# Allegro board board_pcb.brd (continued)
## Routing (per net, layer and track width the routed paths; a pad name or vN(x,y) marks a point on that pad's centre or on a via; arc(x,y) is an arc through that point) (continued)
N30264: length 3
  TOP w0.152: U37.1 73.94,17 73.79,17.15 73.79,17.78 74.27,18.26 R1373.1 R406.2
N30402: length 1.3
  TOP w0.254: 77.09,17.02 76.57,16.5 U37.9
N30450: length 1.9
  TOP w0.254: C1485.2 77.79,16 U37.8
N34682: length 4.2
  TOP w0.249: 32.85,41.57 33.15,41.27 U4.3
  TOP w0.305: 32.85,41.57 32,42.42 32,42.8 31.85,42.95 R1739.1 R14.2
N51448: length 8.1
  TOP w0.152: U135.24 82.16,87.64 82.68,87.12 R1747.1
N51452: length 1.4
  TOP w0.152: D113.2 81.35,80.24 R1747.2
N56281: length 2.1
  TOP w0.305: R1749.1 83.82,51.56
N56705: length 1
  TOP w0.305: R86.2 R1615.1
N56737: length 2.1
  TOP w0.305: U26.7 78.66,53.4 R176.1
N56741: length 2
  TOP w0.305: R176.2 78.11,55.73 R1748.1 78.08,56.72 R1615.2
N57183: length 1.8
  TOP w0.305: U26.8 80.48,52.75 80.87,52.35 R1749.2
N60036: length 1.7
  TOP w0.152: R1751.1 D117.1
N60157: length 1.7
  TOP w0.152: R1752.1 D118.1
N61083: length 1.6
  TOP w0.152: R1755.1 29.44,39.24 D121.1
N61087: length 1.4
  TOP w0.152: D122.1 30.07,43.43 R1756.1
N8840853: length 3.5
  TOP w0.152: U133.21 58.95,20.57 58.04,19.66 58.04,19.46 R1733.1
N8856572: length 2.5
  TOP w0.152: R32.1 C356.2 48.23,49.5 X3.3
N8887240: length 6.9
  TOP w0.152: U1.C12 v2(46.87,66.05) ; R281.2 v2(42.04,67.94)
  BOTTOM w0.152: v2(42.04,67.94) 42.55,67.44 44.32,67.44 45.71,66.05 v2(46.87,66.05)
N8887299: length 5.3
  TOP w0.152: R1224.2 43.41,66.62 44.55,66.62 44.73,66.45 U1.A13
N8887317: length 6
  TOP w0.152: R1225.2 41.81,65.66 43.18,67.03 44.78,67.03 44.97,66.85 46.07,66.85 U1.B13
N8887321: length 9
  TOP w0.152: R1223.2 v2(42.04,70.23) ; U1.E14 v2(48.47,67.65)
  BOTTOM w0.152: v2(48.47,67.65) 48.07,68.05 45.9,68.05 45.67,68.27 45.67,68.68 45.51,68.85 44.79,68.85 43.41,70.23 v2(42.04,70.23)
N8887325: length 8.7
  TOP w0.152: U1.E13 v2(48.47,66.85) ; R1222.2 v2(42.04,69.09)
  BOTTOM w0.152: v2(42.04,69.09) 43.69,69.09 45.53,67.25 48.07,67.25 v2(48.47,66.85)
N8887398: length 7.7
  TOP w0.152: v2(42.04,66.93) 41.91,66.8 R1221.2 ; U1.D12 v2(47.67,66.05)
  BOTTOM w0.152: v2(42.04,66.93) 42.55,66.42 44.7,66.42 45.51,65.61 47.24,65.61 v2(47.67,66.05)
N8915420: length 1.4
  TOP w0.305: U1.U11 v2(58.87,65.25)
  BOTTOM w0.305: v2(58.87,65.25) 59.23,65.61 C1945.2
N8916004: length 1.6
  TOP w0.305: U1.A7 44.88,61.65 v2(44.83,61.59)
  BOTTOM w0.305: C1947.2 45.21,61.21 v2(44.83,61.59)
N8924132: length 3.7
  TOP w0.152: U3.48 22.07,79.84 22.23,79.99 R1766.1
N8924451: length 5.6
  TOP w0.152: U3.38 22.32,74.84 22.61,74.55 22.61,72.16 R1767.1
N8924569: length 2.4
  TOP w0.152: R1768.1 20.02,70.55 U3.36
N16774766: length 3.8
  TOP w0.152: U3.32 18.02,71.54 R1769.1 R946.1
N16774923: length 3.5
  TOP w0.152: R1774.1 R1770.2 16.89,71.37 16.52,71.74 U3.29
N16774927: length 2.9
  TOP w0.152: U3.28 16.02,71.67 R1775.1
N16775135: length 3.7
  TOP w0.152: R1776.1 R1773.1 13.84,70.99 14.52,71.67 U3.25
N16776183: length 4.5
  TOP w0.152: U3.37 22.05,74.34 22.23,74.17 22.23,71.53 R1777.1
N16776304: length 5.4
  TOP w0.152: U3.42 22.73,76.84 24.26,75.31 24.26,74.14 R1783.1
N16776308: length 5
  TOP w0.152: R1778.1 24.87,75.34 22.86,77.34 U3.43
N16776812: length 1.9
  TOP w0.305: X5.1 30.15,75.08 R1781.1
N16777866: length 2.8
  TOP w0.254: R1786.1 13.82,82.55 14.73,82.55 15.02,82.26 U3.11
N16777871: length 5.4
  TOP w0.254: U3.12 14.52,81.79 14.27,82.04 13.31,82.04 R1784.1 11.79,82.91 11.18,82.3 Q18.2
N16777887: length 2.8
  TOP w0.254: U3.14 10.78,79.34 R1855.2
N16778460: length 2.8
  TOP w0.152: R1787.2 10.83,76.34 U3.20
N16778536: length 3.7
  TOP w0.152: R1848.2 R1788.2 10.56,76.84 U3.19
N16779520: length 4.2
  TOP w0.305: R1855.1 8.53,78.99 8,79.53 8,80.26 Q18.1
N16781751: length 33.5
  TOP w0.305: J3.9 22.73,102.37 16.26,102.37 15.49,101.6 9.78,101.6 7.24,99.06 7.24,90.17 10.54,86.87 R1790.2
N16781754: length 22.3
  TOP w0.305: R1791.2 5.71,89.31 5.71,100.08 9.56,103.92 J3.12
N16783015: length 6
  TOP w0.305: v1(19.79,86.74) 19.79,86.03 20.09,85.72 C1961.2 20.89,86.3 21.34,86.74 v1(22.38,86.74)
  BOTTOM w0.305: R1794.1 v1(19.79,86.74) ; R1793.1 v1(22.38,86.74)
N16783029: length 5.4
  TOP w0.305: v1(13.06,86.74) 13.94,85.85 C1962.2 15.3,86.4 v1(15.65,86.74)
  BOTTOM w0.305: R1796.1 v1(13.06,86.74) ; R1795.1 v1(15.65,86.74)
N16791902: length 11.5
  TOP w0.152: U1.E7 v2(48.47,62.05) ; R1797.2 R1798.2 41.76,59.94 v2(42.29,59.41)
  BOTTOM w0.152: v2(42.29,59.41) 42.32,59.44 45.34,59.44 45.53,59.25 47.87,59.25 48.07,59.45 48.07,61.41 48.47,61.81 v2(48.47,62.05)
N16792692: length 3.1
  TOP w0.152: R1854.2 48.69,85.85 S10.1
N16792994: length 2.7
  TOP w0.152: S7.1 85.98,87.78 R1856.2
N16847649: length 2.3
  TOP w0.249: 32.42,37.75 32.65,37.98 U4.5
  TOP w0.305: 32.42,37.75 31.75,37.08 R20.2
N16850956: length 1.4
  TOP w0.381: R1806.2 76.07,9.65 76.2,9.78 D133.2
N16850985: length 1.4
  TOP w0.381: R1807.2 69.09,50.93 69.34,51.18 D132.2
N16872883: length 4.6
  TOP w0.152: U1.N4 v2(55.67,58.85)
  BOTTOM w0.152: v2(55.67,58.85) 55.04,58.85 54.48,58.29 54.48,57.8 54.33,57.65 52.72,57.65 R1782.1
N16886716: length 1.4
  TOP w0.305: U1.D17 v2(47.67,70.05)
  BOTTOM w0.305: C1946.2 47.62,70.09 v2(47.67,70.05)
N16890832: length 5.2
  TOP w0.203: 56.27,21.2 56.89,21.2 56.95,21.26 U133.16
  TOP w0.305: 56.27,21.2 56.15,21.32 55.42,21.32 54.74,20.63 54.74,20.29 R1853.1
N16908117: length 6.5
  TOP w0.152: U2.H3 72.48,63.23 73.91,63.23 74.04,63.09 74.54,63.09 R1851.2
N16908318: length 5.7
  TOP w0.152: U2.J2 73.29,64.03 73.93,64.03 74.17,64.26 74.55,64.26 R1849.2
N16914135: length 1.7
  TOP w0.152: R1626.1 30.53,7.39 D74.1
N16971823:
  vias: v1(104.65,5.71) v1(104.65,4.45) v1(104.65,3.17) v1(105.92,5.71) v1(105.92,4.45) v1(105.92,3.17) v1(107.19,5.71) v1(107.19,4.45) v1(107.19,3.17) v1(108.46,5.71) v1(108.46,4.45) v1(108.46,3.17) v1(109.73,5.71) v1(109.73,4.45) v1(109.73,3.17)
N17017170: length 2.7
  TOP w0.152: U140.4 41.83,42.72 R50.1 R1673.1
N17038390: length 2.5
  TOP w0.305: D134.2 67.46,28.97 R1868.2 68.43,29.59 R1867.1
N17051637: length 2.7
  TOP w0.152: U141.3 v1(55.38,41.43)
  BOTTOM w0.305: R1863.2 55.4,43.26 R1864.1 55.4,41.45 v1(55.38,41.43)
N17051655: length 1.8
  TOP w0.254: U141.5 v1(54.88,37.47)
  BOTTOM w0.305: R1862.2 v1(54.88,37.47)
N17071435: length 1
  TOP w0.305: R1868.1 66.67,29.57 R1869.1
N19175875: length 1.5
  TOP w0.254: C1791.2 89.89,40.25 U8.7
N19175881: length 2.6
  TOP w0.254: U8.8 88.12,41.64 88.39,41.91 89.64,41.91 R1608.2
N19175893: length 3.9
  TOP w0.254: v2(86.6,40.01) v2(86.6,40.44) 86.62,40.46 U8.11 86.62,42.61 v1(86.61,42.62) ; v2(86.6,39.57) 86.62,39.55 U8.2
  TOP w0.305: v2(86.6,39.57) v2(86.6,40.01)
  vias: v1(85.85,42.62)
N19175909: length 1.6
  TOP w0.254: R1605.1 89.63,39.76 U8.6
N19176042: length 3.7
  TOP w0.254: U8.5 88.12,38.37 88.39,38.1 88.77,38.1 89.05,38.38 R1602.1 R1604.1
N19176179: length 2.6
  TOP w0.254: R1599.1 87.12,42.19 U8.10
N19176181: length 3.8
  TOP w0.254: R1599.2 C1779.2 88.84,46.16 89.15,46.48 89.15,46.86 89.63,47.34 D112.1
N19179790: length 1
  TOP w0.254: R1608.1 R1609.1
N19180483: length 3.1
  TOP w0.254: C1789.1 R1606.1 R1607.1 91.72,39.37 R1605.2
N19180998: length 1
  TOP w0.254: C1789.2 93.75,40.39 R1603.2
N19211433: length 4.3
  TOP w0.254: U8.4 87.62,37.98 89.05,36.55 R142.1 89.05,35.1 R85.2
N19540928: length 1
  TOP w0.254: R1607.2 91.82,41.25 R1610.1
N19572988: length 1.8
  TOP w0.305: U132.8 60.16,33.95 60.55,33.55 R1611.2
N19573046: length 2.1
  TOP w0.305: U132.7 58.87,34.6 58.32,35.15 R1477.1
N19573048: length 2
  TOP w0.305: R1613.1 57.76,37.92 R1475.1 57.78,36.93 R1477.2
N19576360: length 1
  TOP w0.305: R1613.2 R1612.2
N88478500: length 2.8
  TOP w0.152: R1742.1 17.17,63.6 S5.1
N88479500: length 2.8
  TOP w0.152: R267.1 8.74,64.82 8.3,64.39 S3.1
N88497910: length 2.8
  TOP w0.152: S6.1 58.6,84.76 R1745.1
N167922400: length 2.7
  TOP w0.152: R1802.1 53.01,84.76 S11.1

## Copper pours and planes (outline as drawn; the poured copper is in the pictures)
1V2 on TOP (solid shape): 69.6,73.76 79.76,73.76 83.67,69.85 83.67,65.35 86.49,62.53 86.49,60.45 88.77,58.17 88.77,56.64 88.71,56.58 84.39,56.58 84.33,56.64 84.33,57.4 83.95,57.78 82.42,57.78 82.3,57.91 82.3,61.98 83.06,61.98 83.06,62.36 82.55,62.36 82.55,61.98 82.3,61.98 82.31,62.02 82.32,62.07 82.32,62.1 82.32,62.61 82.32,62.64 82.31,62.7 82.3,62.73 82.3,62.99 82.17,63.12 81.03,63.12 80.77,63.37 80.77,68.55 77.95,71.37 68.71,71.37 64.52,75.56 63.77,75.56 63.75,75.57 59.47,75.57 59.18,75.85 59.18,77.22 59.56,77.6 65.76,77.6
1V2 on BOTTOM (solid shape): 84.14,64.07 84.14,57.98 83.95,57.78 82.42,57.78 82.3,57.91 82.3,63.12 82.17,63.25 80.9,63.25 80.77,63.37 80.77,63.88 81.03,64.14 84.07,64.14
1V2 on BOTTOM (solid shape): 61.21,75.82 61.21,75.72 59.79,74.3 57.99,74.3 57.78,74.35 57.58,74.3 56.91,74.3 56.71,74.35 56.5,74.3 56.26,74.3 56.19,74.32 56.13,74.32 55.63,74.32 55.56,74.31 55.5,74.3 55.37,74.42 55.37,75.18 55.75,75.56 58.55,75.56 58.56,75.56 58.8,75.56 59.23,76 61.04,76
2V5 on TOP (solid shape): 57.78,45.59 57.78,42.19 57.02,41.43 57.02,40.51 56.85,40.34 55.88,40.34 55.79,40.42 55.79,41.06 55.88,41.15 55.88,44.7 55.8,44.78 55.8,44.96 56.39,44.96 56.39,45.34 56.01,45.34 56.01,44.96 55.8,44.96 55.8,45.64 55.88,45.72 57.66,45.72
2V5 on TOP (solid shape): 55.12,55.88 55.12,54.01 55.09,54 54.92,53.88 54.82,53.69 54.82,53.68 53.85,52.7 53.59,52.7 53.47,52.83 53.47,53.85 54.48,54.86 54.48,55.3 54.48,55.34 54.48,55.75 54.36,55.88 54.36,56.26 54.43,56.34 54.54,56.34 54.61,56.36 54.63,56.36
2V5 on ART03 (solid shape): 54.37,54.21 54.37,52.32 54.4,52.19 54.48,52.07 56.39,50.16 56.42,50.13 58.04,48.51 58.04,44.07 57.78,43.81 55.5,43.81 55.24,44.07 55.24,48.72 53.34,50.62 53.34,54.1 53.47,54.23 54.36,54.23
3V3 on TOP (solid shape): 9.6,69.65 9.6,68.83 9.65,68.78 9.65,67.94 9.53,67.82 7.49,67.82 7.37,67.94 7.37,68.96 9.4,68.96 9.4,69.34 9.02,69.34 9.02,68.96 7.37,68.96 7.37,69.6 7.49,69.72 9.53,69.72
3V3 on TOP (solid shape): 41.27,43.31 41.27,40.77 41.15,40.64 40.13,40.64 39.88,40.89 39.88,42.67 40.89,42.67 40.89,43.18 40.51,43.18 40.51,42.67 39.88,42.67 39.88,43.31 40.01,43.43 41.15,43.43
3V3 on TOP (solid shape): 51.94,105.66 51.94,103.89 50.29,102.23 50.27,102.24 50.23,102.25 50.19,102.26 50.16,102.26 49.66,102.26 49.63,102.26 49.57,102.25 49.53,102.23 48.64,102.23 48.51,102.36 48.51,102.49 49.91,102.49 49.91,103 49.53,103 49.53,102.49 48.51,102.49 48.51,103.63 50.67,105.79 51.82,105.79
3V3 on TOP (solid shape): 65.38,87.37 65.4,87.35 65.45,87.32 65.5,87.29 65.56,87.27 65.62,87.26 65.77,87.26 66.29,86.74 68.45,86.74 68.61,86.59 68.61,85.7 68.45,85.55 63.25,85.55 63.12,85.67 63.12,85.72 65.66,85.72 65.66,86.23 65.28,86.23 65.28,85.72 63.12,85.72 63.12,87.38 63.25,87.5 65.25,87.5
3V3 on TOP (solid shape): 37.29,9.7 37.29,4.78 36.58,4.06 35.31,4.06 35.18,4.19 35.18,6.35 35.56,6.73 35.56,7.11 37.08,7.11 37.08,7.49 36.7,7.49 36.7,7.11 35.56,7.11 35.56,8.13 37.08,8.13 37.08,8.51 36.7,8.51 36.7,8.13 35.56,8.13 35.56,9.91 35.69,10.03 36.96,10.03
3V3 on TOP (solid shape): 77.34,7.7 80.44,7.7 80.64,7.49 80.64,6.48 80.26,6.1 79.5,6.1 79.38,5.97 79.38,5.84 79.36,5.8 79.35,5.74 79.35,5.71 79.35,5.21 79.35,5.18 79.25,5.08 76.83,5.08 76.71,5.21 76.71,5.46 79.12,5.46 79.12,5.84 78.74,5.84 78.74,5.46 76.71,5.46 76.71,7.11 78.99,7.11 78.99,7.49 78.61,7.49 78.61,7.11 77.98,7.11 77.98,7.49 77.6,7.49 77.6,7.11 76.71,7.11 77.32,7.72
3V3 on TOP (solid shape): 44.45,91.06 44.45,89.79 44.32,89.66 44.3,89.67 44.26,89.68 44.22,89.69 44.2,89.69 43.69,89.69 43.66,89.69 43.6,89.68 43.56,89.66 43.3,89.66 43.27,89.68 43.21,89.69 43.18,89.69 42.67,89.69 42.64,89.69 42.59,89.68 42.55,89.66 41.27,89.66 41.02,89.92 44.32,89.92 44.32,90.42 43.94,90.42 43.94,89.92 43.31,89.92 43.31,90.42 42.93,90.42 42.93,89.92 41.02,89.92 40.89,90.04 40.89,91.06 41.02,91.19 44.32,91.19
3V3 on TOP (solid shape): 60.33,36.96 60.33,35.99 60.27,35.94 60.27,35.76 60.25,35.74 59.06,35.74 59.03,35.73 58.89,35.69 58.79,35.58 58.77,35.56 58.53,35.56 58.45,35.59 58.39,35.61 58.37,35.61 58.34,35.64 58.34,36.25 58.5,36.4 58.83,36.4 59.04,36.49 59.13,36.7 59.13,37.03 59.18,37.08 60.2,37.08
3V3 on TOP (solid shape): 5.23,62.09 5.27,62.08 5.31,62.08 5.33,62.08 5.84,62.08 5.87,62.08 5.93,62.09 5.97,62.1 6.23,62.1 6.26,62.09 6.32,62.08 6.35,62.08 6.86,62.08 6.89,62.08 6.94,62.09 6.98,62.1 7.75,62.1 7.87,61.98 7.87,59.05 7.37,58.55 5.46,58.55 5.08,58.93 5.08,61.34 6.99,61.34 6.99,61.85 6.6,61.85 6.6,61.34 5.97,61.34 5.97,61.85 5.59,61.85 5.59,61.34 5.08,61.34 5.08,61.98 5.21,62.1
3V3 on TOP (solid shape): 57.12,38.3 57.12,34.82 57.4,34.54 58.04,34.54 58.17,34.42 58.17,33.66 56.77,32.26 56.52,32.26 56.34,32.44 56.34,34.47 56.06,34.75 56.06,35.18 56.64,35.18 56.64,35.56 56.26,35.56 56.26,35.18 56.06,35.18 56.06,35.94 56.64,35.94 56.64,36.32 56.26,36.32 56.26,35.94 56.06,35.94 56.06,37.52 55.8,37.78 55.8,38.11 55.81,38.2 55.81,38.62 55.88,38.69 56.43,38.69 56.49,38.7 56.73,38.7
3V3 on TOP (solid shape): 66.17,48.77 66.17,45.47 66.42,45.21 68.45,45.21 68.83,45.59 68.83,48.01 69.09,48.26 72.9,48.26 73.03,48.13 73.03,44.32 72.64,43.94 70.48,43.94 70.1,43.56 67.44,43.56 67.18,43.31 67.18,40.39 68.45,39.12 68.45,37.85 68.39,37.79 63.96,37.79 63.96,37.72 63.88,37.72 63.5,37.34 63.5,36.83 63.37,36.7 62.87,36.7 62.74,36.83 62.74,38.1 61.98,38.86 61.98,44.58 62.74,44.58 62.74,44.96 62.23,44.96 62.23,44.58 61.98,44.58 61.99,44.62 62,44.67 62,44.7 62,45.21 62,45.24 61.99,45.3 61.98,45.34 61.98,45.59 61.85,45.72 60.58,45.72 60.45,45.85 60.45,46.48 60.58,46.61 62.74,46.61 62.99,46.86 62.99,47.5 63.01,47.54 63.02,47.6 63.02,47.62 63.02,47.88 63.75,47.88 63.75,48.26 63.25,48.26 63.25,47.88 63.02,47.88 63.02,48.13 63.02,48.16 63.01,48.22 62.99,48.26 62.99,48.51 63.07,48.59 63.53,48.59 63.55,48.59 63.61,48.6 63.66,48.62 63.7,48.64 63.75,48.64 64.01,48.9 66.04,48.9
3V3 on BOTTOM (solid shape): 64.9,87.25 64.9,85.72 64.77,85.6 63.37,85.6 63.12,85.85 63.12,87.09 63.4,87.37 64.77,87.37
3V3 on BOTTOM (solid shape): 73.03,47.24 73.03,44.45 72.9,44.32 71.37,44.32 71.25,44.45 71.25,47.24 71.5,47.5 72.77,47.5
3V3 on BOTTOM (solid shape): 52.17,103.05 53.57,103.05 53.85,102.77 53.85,100.79 53.64,100.58 53.01,100.58 52.83,100.76 52.83,101.93 52.58,102.18 48.97,102.18 48.77,102.39 48.77,103.68 48.95,103.86 51.36,103.86
3V3 on BOTTOM (solid shape): 66.17,47.62 66.17,43.81 65.79,43.43 62.36,43.43 61.72,44.07 61.72,45.72 61.59,45.85 60.58,45.85 60.45,45.97 60.45,46.86 60.64,47.05 62.29,47.05 63.12,47.88 65.91,47.88
3V3 on BOTTOM (solid shape): outline of 321 points within 56.26,32.26 64.14,39.24
3V3 on ART06 (solid shape): outline of 16589 points within 4.06,4.57 97.16,104.27
3V9 on TOP (solid shape): 28.17,46.91 29.06,46.91 29.24,46.74 33.05,46.74 33.32,46.46 33.32,45.54 33.66,45.21 33.66,42.8 34.42,42.04 34.42,40.51 34.29,40.39 33.66,40.39 33.53,40.51 33.53,41.53 32.51,42.55 32.51,44.32 32.26,44.58 30.48,44.58 30.35,44.7 31.37,44.7 31.37,45.09 30.99,45.09 30.99,44.7 30.35,44.7 30.23,44.83 28.57,44.83 27.69,45.72 33.02,45.72 33.02,46.1 32.64,46.1 32.64,45.72 27.69,45.72 27.56,45.85 24,45.85 23.88,45.97 23.88,46.35 28.96,46.35 28.96,46.74 28.57,46.74 28.57,46.35 23.88,46.35 23.88,47.12 24.13,47.37 27.71,47.37
5V0 on TOP (solid shape): 73.91,38.1 73.91,34.29 73.79,34.16 71.12,34.16 70.99,34.29 70.99,37.97 71.25,38.23 73.79,38.23
5V0 on TOP (solid shape): 94.23,56.9 94.23,53.09 94.11,52.96 91.44,52.96 91.31,53.09 91.31,56.77 91.57,57.02 94.11,57.02
5V0 on TOP (solid shape): 121.41,104.65 121.41,103.12 121.36,103.07 119.04,103.07 119.04,104.31 119.51,104.78 121.28,104.78
5V0 on TOP (solid shape): 135.25,103.12 135.25,93.98 135,93.73 133.73,93.73 133.35,94.11 133.35,98.17 132.46,99.06 132.46,99.82 132.97,99.82 132.97,100.2 132.59,100.2 132.59,99.82 132.46,99.82 132.46,103.25 132.59,103.38 135,103.38
5V0 on TOP (solid shape): 83.82,47.62 83.82,42.42 83.19,41.78 83.19,39.24 82.93,38.99 75.31,38.99 74.93,39.37 74.93,45.09 75.82,45.09 75.82,45.47 75.44,45.47 75.44,45.09 74.93,45.09 74.93,45.47 75.18,45.72 75.44,45.72 75.48,45.71 75.54,45.69 75.56,45.69 76.07,45.69 76.1,45.69 76.58,45.21 80.39,45.21 80.64,45.47 80.64,47.37 81.15,47.88 83.57,47.88
5V0 on TOP (solid shape): 34.39,38.76 34.39,37.39 34.11,37.11 34.11,35.2 33.71,34.8 33.71,33.27 33.58,33.15 30.86,33.15 30.73,33.27 30.73,34.8 31.01,35.08 32.18,35.08 32.33,35.23 32.33,35.31 33.91,35.31 33.91,35.69 33.53,35.69 33.53,35.31 32.33,35.31 32.33,36.32 33.91,36.32 33.91,36.7 33.53,36.7 33.53,36.32 32.33,36.32 32.33,36.93 33.5,38.1 33.5,38.73 33.63,38.86 34.29,38.86
5V0 on BOTTOM (solid shape): 75.48,45.71 75.54,45.69 75.56,45.69 76.07,45.69 76.1,45.69 76.58,45.21 80.52,45.21 80.64,45.09 80.64,42.29 80.39,42.04 75.18,42.04 74.93,42.29 74.93,45.09 75.82,45.09 75.82,45.47 75.44,45.47 75.44,45.09 74.93,45.09 74.93,45.47 75.18,45.72 75.44,45.72
5V0 on BOTTOM (solid shape): 122.05,106.17 122.05,103.12 121.54,102.62 119.63,102.62 119.38,102.87 119.38,103.12 119.89,103.12 119.89,103.5 119.51,103.5 119.51,103.12 119.38,103.12 119.38,103.76 119.89,103.76 119.89,104.14 119.51,104.14 119.51,103.76 119.38,103.76 119.38,104.52 119.63,104.78 120.4,104.78 120.78,105.16 120.78,106.3 120.9,106.43 121.79,106.43
5V0 on POWER05 (solid shape): outline of 14480 points within 23.24,29.59 135.51,105.54
AGND on TOP (solid shape): 12.57,24.13 12.57,20.7 12.45,20.57 10.29,20.57 10.16,20.7 10.16,24.26 10.29,24.38 12.32,24.38
AGND on TOP (solid shape): 29.34,31.75 29.34,29.08 29.21,28.96 28.07,28.96 27.94,29.08 27.94,31.75 28.07,31.88 29.21,31.88
AGND on TOP (solid shape): 35.56,45.72 35.56,39.52 35.18,39.14 32.59,39.14 30.96,40.77 30.96,41.4 31.11,41.55 32.23,41.55 32.77,41.02 32.77,40.26 32.92,40.11 34.85,40.11 35.08,40.34 35.08,41.88 34.04,42.93 34.04,45.31 33.76,45.59 34.42,45.59 34.42,46.1 33.91,46.1 33.91,45.59 33.76,45.59 33.71,45.64 33.71,46.56 33.12,47.14 32.36,47.14 32.13,47.37 29.59,47.37 29.51,47.29 28.4,47.29 28.32,47.37 28.32,47.5 28.96,47.5 28.96,47.88 28.57,47.88 28.57,47.5 28.32,47.5 28.32,48.01 28.83,48.51 32.77,48.51
AGND on TOP (solid shape): outline of 445 points within 0.51,0.51 25.91,57.53
AGND on BOTTOM (solid shape): outline of 1654 points within 0.51,0.51 35.56,57.53
AGND on GND02 (solid shape): outline of 1717 points within 0.51,0.51 35.56,57.53
AGND on ART03 (solid shape): outline of 1750 points within 0.51,0.51 35.56,64.64
AGND on GND04 (solid shape): outline of 1717 points within 0.51,0.51 35.56,57.53
AGND on POWER05 (solid shape): outline of 1717 points within 0.51,0.51 35.56,57.53
AGND on ART06 (solid shape): outline of 1707 points within 0.51,0.51 35.56,57.53
AGND on GND07 (solid shape): outline of 1717 points within 0.51,0.51 35.56,57.53
AGND on ART08 (solid shape): outline of 1717 points within 0.51,0.51 35.56,57.53
AGND on GND09 (solid shape): outline of 1717 points within 0.51,0.51 35.56,57.53
AVDD1V8 on TOP (solid shape): 32.89,87.63 32.89,83.82 32.77,83.69 24.89,83.69 24.64,83.95 24.64,88.52 24.89,88.77 31.75,88.77
AVDD1V8 on POWER05 (solid shape): outline of 1568 points within 12.32,76.96 35.31,93.98
GND on TOP (solid shape): 9.91,44.7 9.91,43.43 9.78,43.31 5.97,43.31 5.84,43.43 5.84,44.7 5.97,44.83 9.78,44.83
GND on TOP (solid shape): 27.81,49.78 27.81,48.77 27.43,48.39 24,48.39 23.88,48.51 23.88,49.78 24,49.91 27.69,49.91
GND on TOP (solid shape): 32.38,31.62 32.38,29.08 32.26,28.96 30.48,28.96 30.35,29.08 30.35,31.75 30.48,31.88 32.13,31.88
GND on TOP (solid shape): 34.16,94.11 34.16,92.08 33.91,91.82 32.26,91.82 32.13,91.95 32.13,94.11 32.26,94.23 34.04,94.23
GND on TOP (solid shape): 37.97,80.01 37.97,77.47 37.85,77.34 36.45,77.34 36.32,77.47 36.32,80.01 36.45,80.14 37.85,80.14
GND on TOP (solid shape): 41.02,94.74 41.02,91.82 40.89,91.69 40.39,91.69 40.26,91.82 40.26,94.74 40.39,94.87 40.89,94.87
GND on TOP (solid shape): 42.04,33.15 42.04,30.48 41.91,30.35 35.43,30.35 35.18,30.61 35.18,31.97 36.48,33.27 41.91,33.27
GND on TOP (solid shape): 53.98,30.61 53.98,25.65 53.85,25.53 52.2,25.53 52.07,25.65 52.07,30.61 52.32,30.86 53.72,30.86
GND on TOP (solid shape): 84.71,25.27 84.71,21.08 84.45,20.83 81.53,20.83 81.41,20.95 81.41,25.27 81.66,25.53 84.45,25.53
GND on TOP (solid shape): 73.35,13.77 73.35,12.65 73.28,12.57 72.9,12.57 72.77,12.7 71.88,12.7 71.75,12.83 71.75,13.54 71.93,13.72 72.77,13.72 72.9,13.84 73.28,13.84
GND on TOP (solid shape): 50.29,101.85 50.29,100.33 50.16,100.2 48.64,100.2 48.51,100.33 48.51,101.22 49.91,101.22 49.91,101.73 49.53,101.73 49.53,101.22 48.51,101.22 48.51,101.85 48.59,101.93 50.22,101.93
GND on TOP (solid shape): 87.76,15.37 87.76,12.19 87.38,11.81 85.22,11.81 85.09,11.94 85.09,13.84 87.63,13.84 87.63,14.22 87.25,14.22 87.25,13.84 85.09,13.84 85.09,15.37 85.22,15.49 87.63,15.49
GND on TOP (solid shape): 46.23,20.19 46.23,16.89 46.1,16.76 42.42,16.76 42.29,16.89 42.29,18.54 42.16,18.67 42.16,19.94 42.42,20.19 44.45,20.19 44.7,20.45 45.97,20.45
GND on TOP (solid shape): 80.26,48.26 80.26,45.72 80.14,45.59 76.83,45.59 76.33,46.1 75.56,46.1 75.44,46.23 76.2,46.23 76.2,46.61 75.82,46.61 75.82,46.23 75.44,46.23 75.44,48.13 75.69,48.39 80.14,48.39
GND on TOP (solid shape): 41.27,44.96 41.27,43.81 41.21,43.75 40.32,43.75 40.13,43.94 40.89,43.94 40.89,44.45 40.51,44.45 40.51,43.94 40.13,43.94 39.5,44.58 39.5,44.96 39.62,45.09 41.15,45.09
GND on TOP (solid shape): 68.55,85.09 68.55,84.12 68.48,84.05 66.9,84.05 66.17,83.31 63.25,83.31 63.12,83.44 63.12,84.45 65.66,84.45 65.66,84.96 65.28,84.96 65.28,84.45 63.12,84.45 63.12,85.09 63.2,85.17 68.48,85.17
GND on TOP (solid shape): 68.45,54.36 68.45,45.85 68.2,45.59 66.8,45.59 66.55,45.85 66.55,48.45 66.55,48.46 66.55,48.87 66.55,48.88 66.55,49.35 66.6,49.4 66.6,53.47 67.31,53.47 67.31,53.85 66.8,53.85 66.8,53.47 66.6,53.47 66.6,54.41 66.67,54.48 68.33,54.48
GND on TOP (solid shape): 23.88,75.15 23.88,74.14 23.88,74.13 23.88,73.41 24.77,72.52 25.3,72.52 25.3,72.24 25.33,72.09 25.41,71.97 26.29,71.09 26.29,70.74 26.16,70.74 25.27,71.63 24.77,71.63 23.37,73.02 23.37,75.18 23.5,75.31 23.72,75.31
GND on TOP (solid shape): 41.91,57.4 41.91,56.39 41.78,56.26 40.64,56.26 40.39,56.01 38.61,56.01 38.35,55.75 37.72,55.75 37.47,56.01 35.69,56.01 35.56,56.13 35.56,56.52 41.4,56.52 41.4,56.9 41.02,56.9 41.02,56.52 35.56,56.52 35.56,57.4 35.71,57.56 41.76,57.56
GND on TOP (solid shape): 57.09,31.43 57.09,30.67 57.28,30.48 57.28,27.3 57.15,27.18 56.9,27.18 56.39,26.67 54.48,26.67 54.36,26.8 54.36,30.73 56.9,30.73 56.9,31.11 56.52,31.11 56.52,30.73 54.36,30.73 54.36,31.37 54.61,31.62 56.9,31.62
GND on TOP (solid shape): 69.22,9.53 69.22,8 70.1,7.11 72.77,7.11 73.15,6.73 73.15,4.19 73.41,3.94 78.36,3.94 78.74,3.56 78.74,2.16 79.63,1.27 79.63,0.64 79.5,0.51 67.39,0.51 67.31,0.59 67.31,8.13 67.06,8.38 67.06,9.53 67.18,9.65 69.09,9.65
GND on TOP (solid shape): 39.75,48.39 40.89,48.39 41.02,48.26 41.02,47.37 40.77,47.12 38.86,47.12 38.79,47.19 38.79,47.5 39.37,47.5 39.37,47.88 38.99,47.88 38.99,47.5 38.79,47.5 38.79,48.13 39.37,48.13 39.37,48.51 38.99,48.51 38.99,48.13 38.79,48.13 38.79,48.69 38.86,48.77 39.37,48.77
GND on TOP (solid shape): 42.8,40.26 42.8,38.1 42.34,37.64 42.34,37.21 42.27,37.13 41.58,37.13 41.5,37.21 41.5,37.47 42.16,37.47 42.16,37.85 41.78,37.85 41.78,37.47 41.5,37.47 41.5,37.92 41.66,38.07 41.66,40.26 41.78,40.39 42.67,40.39
GND on TOP (solid shape): 36.2,37.72 36.2,34.67 35.18,33.66 34.59,33.66 34.42,33.83 34.42,35.26 34.47,35.31 35.05,35.31 35.05,35.69 34.67,35.69 34.67,35.31 34.47,35.31 34.47,36.32 35.05,36.32 35.05,36.7 34.67,36.7 34.67,36.32 34.47,36.32 34.47,37.01 34.73,37.27 34.73,37.66 34.92,37.85 36.07,37.85
GND on TOP (solid shape): 39.88,8.89 39.88,5.46 39.75,5.33 37.97,5.33 37.62,5.69 37.62,6.73 38.23,6.73 38.23,7.11 37.85,7.11 37.85,6.73 37.62,6.73 37.62,7.75 38.23,7.75 38.23,8.13 37.85,8.13 37.85,7.75 37.62,7.75 37.62,9.04 37.72,9.14 39.62,9.14
GND on TOP (solid shape): 55.75,9.78 55.75,0.59 55.67,0.51 27.01,0.51 26.92,0.59 26.92,3.43 27.18,3.68 39.24,3.68 40.26,4.7 40.26,8.13 41.27,9.14 43.43,9.14 43.56,9.02 43.56,8.51 43.31,8.26 43.31,1.52 43.56,1.27 50.67,1.27 51.08,1.68 51.08,8.1 50.16,9.02 50.16,10.16 50.55,10.54 54.99,10.54
GND on TOP (solid shape): 91.06,59.94 91.06,56.95 91.01,56.9 91.01,52.96 91.06,52.91 91.06,52.07 90.93,51.94 86.03,51.94 85.9,52.07 85.72,52.07 85.68,52.08 85.63,52.1 85.6,52.1 85.19,52.1 85.09,52.2 85.09,52.32 85.72,52.32 85.72,52.83 85.34,52.83 85.34,52.32 85.09,52.32 85.09,53.47 85.22,53.59 89.03,53.59 89.15,53.72 89.15,58.29 88.01,59.44 88.01,59.82 88.27,60.07 90.93,60.07
GND on TOP (solid shape): 37.29,91.11 37.29,88.21 37.21,88.14 35.05,88.14 34.92,88.27 34.92,88.39 37.08,88.39 37.08,88.77 36.58,88.77 36.58,88.39 34.92,88.39 34.92,89.41 37.08,89.41 37.08,89.79 36.58,89.79 36.58,89.41 34.92,89.41 34.92,89.79 35.18,90.04 35.69,90.04 35.81,90.17 35.81,90.42 37.08,90.42 37.08,90.81 36.58,90.81 36.58,90.42 35.81,90.42 35.81,90.9 36.1,91.19 37.21,91.19
GND on TOP (solid shape): 45.34,15.62 45.34,13.87 44.83,13.36 41,13.36 40.89,13.46 40.89,13.59 44.7,13.59 44.7,13.97 44.32,13.97 44.32,13.59 43.69,13.59 43.69,13.97 43.31,13.97 43.31,13.59 42.67,13.59 42.67,13.97 42.29,13.97 42.29,13.59 41.66,13.59 41.66,13.97 41.27,13.97 41.27,13.59 40.89,13.59 40.89,15.62 41.02,15.75 45.21,15.75
GND on TOP (solid shape): 73.53,43.05 73.53,39.24 73.03,38.73 70.99,38.73 70.74,38.48 70.74,38.15 70.69,38.1 70.69,34.16 70.74,34.11 70.74,33.27 70.61,33.15 65.71,33.15 65.58,33.27 65.4,33.27 65.36,33.29 65.31,33.3 65.28,33.3 64.87,33.3 64.77,33.4 64.77,33.53 65.41,33.53 65.41,34.04 65.02,34.04 65.02,33.53 64.77,33.53 64.77,34.67 64.9,34.8 68.71,34.8 68.83,34.92 68.83,38.84 70.85,40.86 70.85,41.03 70.87,41.05 70.87,43.18 70.99,43.31 73.28,43.31
GND on TOP (solid shape): 85.72,41.91 86.11,41.91 86.23,41.78 86.23,37.97 85.72,37.47 85.72,32.51 85.34,32.13 84.07,32.13 83.82,31.88 83.82,30.23 83.69,30.1 80.9,30.1 80.26,30.73 73.91,30.73 73.41,30.23 73.41,27.18 73.28,27.05 69.98,27.05 69.72,27.3 69.72,30.35 69.91,30.54 72.96,30.54 75.31,32.89 75.31,34.67 75.56,34.92 83.06,34.92 83.19,35.05 83.19,37.59 83.69,38.1 83.69,41.53 84.33,42.16 85.47,42.16
GND on TOP (solid shape): 59,19.68 59,13.92 59.08,13.84 59.08,13.41 59,13.34 57.91,13.34 57.78,13.46 57.78,15.68 57.8,15.7 57.82,15.74 57.83,15.78 57.84,15.83 57.84,15.85 57.84,17.17 57.84,17.2 57.83,17.25 57.81,17.3 57.78,17.34 57.78,17.46 57.81,17.49 57.83,17.55 57.84,17.6 57.84,17.63 57.84,18.54 58.8,18.54 58.8,18.92 58.42,18.92 58.42,18.54 57.84,18.54 57.84,18.71 58.31,19.19 58.33,19.21 58.36,19.26 58.39,19.31 58.41,19.37 58.42,19.43 58.42,19.5 58.78,19.86 58.83,19.86
GND on TOP (solid shape): 75.56,54.61 75.56,49.66 75.18,49.27 75.11,49.22 74.61,48.71 74.55,48.64 74.42,48.51 74.42,43.56 74.3,43.43 73.77,43.43 73.75,43.45 73.71,43.49 73.67,43.51 73.62,43.53 73.57,43.55 73.55,43.55 73.53,43.56 73.53,48.9 73.41,49.02 73.41,52.45 73.42,52.49 73.43,52.55 73.43,52.58 73.43,52.83 74.17,52.83 74.17,53.21 73.66,53.21 73.66,52.83 73.43,52.83 73.43,53.09 73.43,53.12 73.42,53.17 73.41,53.21 73.41,54.61 73.53,54.74 75.44,54.74
GND on TOP (solid shape): 80.77,5.59 80.77,5.21 81.03,4.95 81.16,4.95 81.19,4.94 81.25,4.93 81.28,4.93 81.79,4.93 81.82,4.93 81.87,4.94 81.91,4.95 82.17,4.95 82.21,4.94 82.27,4.93 82.3,4.93 82.8,4.93 82.83,4.93 82.87,4.93 82.91,4.94 82.93,4.95 83.06,4.83 83.06,3.05 82.8,2.79 79.88,2.79 79.63,3.05 79.63,4.19 82.55,4.19 82.55,4.7 82.17,4.7 82.17,4.19 81.92,4.19 81.92,4.7 81.53,4.7 81.53,4.19 79.63,4.19 79.63,5.03 79.68,5.08 79.68,5.64 79.76,5.71 80.64,5.71
GND on TOP (solid shape): 60.45,45.41 61.58,45.41 61.66,45.34 61.66,44.34 61.52,44.2 61.52,38.73 62.36,37.9 62.36,36.58 62.87,36.07 62.87,35.84 62.76,35.74 61.52,35.74 61.5,35.72 61.49,35.71 61.34,35.71 61.21,35.59 61.21,34.67 61.09,34.54 60.71,34.54 60.63,34.62 60.62,34.8 60.62,34.85 60.6,34.89 60.58,34.94 60.55,34.98 60.52,35.01 60.48,35.04 60.44,35.06 60.39,35.08 60.34,35.08 60.32,35.08 59.15,35.08 59.05,35.18 59.05,35.31 59.17,35.42 60.32,35.42 60.34,35.42 60.39,35.42 60.45,35.43 60.48,35.47 60.5,35.48 60.54,35.51 60.56,35.54 60.6,35.6 60.62,35.64 60.62,35.7 60.63,35.86 60.71,35.94 60.71,37.08 60.33,37.47 59.46,37.47 59.31,37.62 59.31,44.58 61.47,44.58 61.47,44.96 60.96,44.96 60.96,44.58 59.31,44.58 59.31,45 59.75,45.43 60.43,45.43
GND on TOP (solid shape): 75.12,17.77 75.21,17.72 75.31,17.7 75.82,17.7 75.93,17.72 76.02,17.78 76.2,17.78 76.33,17.65 76.33,17.02 76.24,16.93 75.75,16.93 75.45,16.81 75.32,16.5 75.34,16.37 75.4,16.25 75.34,16.13 75.32,16 75.45,15.7 75.75,15.57 76.63,15.57 76.71,15.49 76.71,13.08 76.58,12.95 75.44,12.95 75.18,13.21 75.18,13.97 74.85,14.3 74.85,15.11 74.8,15.16 74.8,15.32 74.98,15.49 74.8,15.67 74.8,17.53 75.06,17.78 75.11,17.78
GND on TOP (solid shape): 81.75,62.7 81.95,62.7 81.99,62.66 81.99,61.87 81.84,61.72 81.84,57.53 82.22,57.15 83.19,57.15 83.39,56.95 83.39,54.61 83.31,54.53 81.84,54.53 81.82,54.51 81.81,54.51 81.66,54.51 81.53,54.38 81.53,53.47 81.41,53.34 81.03,53.34 80.95,53.42 80.94,53.6 80.94,53.65 80.92,53.69 80.9,53.73 80.87,53.77 80.84,53.81 80.8,53.83 80.76,53.86 80.71,53.87 80.66,53.88 80.64,53.88 79.47,53.88 79.38,53.98 79.38,54.1 79.49,54.21 80.64,54.21 80.66,54.21 80.71,54.22 80.77,54.23 80.83,54.28 80.88,54.32 80.92,54.39 80.94,54.44 80.94,54.49 80.95,54.52 80.95,54.87 80.94,54.9 80.94,54.95 80.92,55 80.9,55.04 80.9,55.14 79.63,56.41 79.63,61.98 81.79,61.98 81.79,62.36 81.28,62.36 81.28,61.98 79.63,61.98 80.39,62.74 81.71,62.74
GND on TOP (solid shape): 65.91,30.73 65.91,26.29 65.79,26.16 64.24,26.16 63.22,25.15 63.22,22.12 64.01,21.34 66.8,21.34 67.06,21.08 67.06,14.1 66.93,13.97 64.64,13.97 64.52,14.1 64.52,20.57 64.17,20.92 63.84,20.92 62.48,22.28 61.85,22.28 61.65,22.48 62.48,22.48 62.48,22.86 62.1,22.86 62.1,22.48 61.65,22.48 61.21,22.91 61.21,23.09 61.04,23.27 58.42,23.27 58.15,23 57.34,23 57.23,23.11 57.23,24.21 57.38,24.36 58.09,24.36 58.24,24.21 58.24,23.55 58.32,23.47 61.06,23.47 61.25,23.66 61.25,23.88 62.48,23.88 62.48,24.26 62.1,24.26 62.1,23.88 61.25,23.88 61.25,23.89 61.82,24.46 62.64,24.46 62.79,24.61 62.79,25.65 63.12,25.98 63.12,30.73 63.25,30.86 65.79,30.86
GND on TOP (solid shape): 43.43,54.1 43.43,53.98 43.33,53.87 42.21,53.87 42.07,53.84 41.95,53.76 41.19,53.01 40.92,53.01 40.84,53 40.77,52.97 40.69,53 40.61,53.01 40.11,53.01 39.92,52.94 39.81,52.77 39.81,52.76 39.75,52.7 39.75,52.07 39.62,51.94 39.62,49.53 39.75,49.4 43.69,49.4 43.81,49.53 43.81,49.65 43.82,49.72 43.82,51.5 43.81,51.56 43.81,51.94 43.69,52.07 43.69,52.45 43.81,52.58 44.07,52.58 44.21,52.72 44.27,52.75 44.31,52.79 45.75,54.23 45.94,54.23 45.97,54.15 45.97,53.72 44.22,51.97 44.14,51.85 44.11,51.7 44.11,49.48 43.4,48.77 39.88,48.77 39.16,49.48 39.17,49.53 39.17,50.8 39.15,50.89 39.12,50.97 39.12,52.83 39.43,53.14 40.07,53.14 40.12,53.15 40.18,53.16 41.02,53.16 42.16,54.3 43.23,54.3
GND on TOP (solid shape): 25.4,76.07 32.89,76.07 33.02,75.95 33.02,70.99 32.77,70.74 31.95,70.74 31.94,70.74 31.63,70.74 31.62,70.74 30.73,70.74 30.72,70.74 30.41,70.74 30.4,70.74 29.51,70.74 29.5,70.74 29.19,70.74 29.18,70.74 28.29,70.74 28.28,70.74 27.21,70.74 27.05,70.9 27.05,71.25 27.05,71.31 27.03,71.37 27.05,71.46 27.13,71.5 30.83,71.5 30.84,71.47 30.95,71.34 31.11,71.3 31.62,71.3 31.81,71.36 31.92,71.53 31.92,71.55 32.13,71.75 32.13,72.8 32.19,72.92 32.21,73.05 32.21,73.89 32.19,74.02 32.13,74.14 32.13,75.44 32,75.56 31.83,75.56 31.73,75.62 31.62,75.64 31.11,75.64 31.01,75.62 30.91,75.56 28.32,75.56 28.19,75.44 28.19,75.26 28.17,75.26 28.17,74.28 27.94,74.04 26.67,74.04 26.42,74.3 26.42,74.93 26.04,75.31 25.25,75.31 25.25,75.36 25.21,75.49 25.14,75.61 23.13,77.61 23.01,77.69 22.86,77.72 22.74,77.72 22.61,77.85 22.61,78.11 22.73,78.23 23.24,78.23
GND on TOP (solid shape): outline of 124 points within 53.47,32.13 56.39,45.75
GND on TOP (solid shape): outline of 99 points within 45.21,46.61 52.7,56.01
GND on TOP (solid shape): outline of 548 points within 0.51,58.55 67.44,109.49
GND on TOP (solid shape): outline of 765 points within 66.67,0.51 139.49,109.49
GND on BOTTOM (solid shape): 57.28,39.62 57.28,38.61 57.02,38.35 54.86,38.35 54.74,38.48 54.74,39.75 54.86,39.88 57.02,39.88
GND on BOTTOM (solid shape): 64.9,84.96 64.9,83.57 64.77,83.44 63.25,83.44 63.12,83.57 63.12,84.96 63.25,85.09 64.77,85.09
GND on BOTTOM (solid shape): 89.79,9.65 89.79,6.86 89.41,6.48 87,6.48 86.61,6.86 86.61,9.6 86.92,9.91 89.53,9.91
GND on BOTTOM (solid shape): 67.06,21.21 67.06,15.75 66.93,15.62 64.39,15.62 64.26,15.75 64.26,21.08 64.52,21.34 66.93,21.34
GND on BOTTOM (solid shape): 68.45,54.36 68.45,45.85 68.2,45.59 66.8,45.59 66.55,45.85 66.55,50.37 66.6,50.42 66.6,54.41 66.67,54.48 68.33,54.48
GND on BOTTOM (solid shape): 50.93,34.54 50.93,32.64 50.74,32.45 50.36,32.45 50.29,32.38 46.99,32.38 46.86,32.51 46.86,34.92 47.12,35.18 50.29,35.18
GND on BOTTOM (solid shape): 75.56,54.61 75.56,49.66 74.42,48.51 74.42,43.56 74.3,43.43 73.66,43.43 73.53,43.56 73.53,48.9 73.41,49.02 73.41,54.61 73.53,54.74 75.44,54.74
GND on BOTTOM (solid shape): 25.4,52.07 27.69,52.07 28.22,51.54 28.22,49.25 27.35,48.39 11.09,48.39 10.29,47.58 10.29,35.9 10.08,35.69 4.78,35.69 3.94,36.53 3.94,52.83 4.57,53.47 24,53.47
GND on BOTTOM (solid shape): 57.28,31.37 57.28,28.19 57.15,28.07 56.26,28.07 56.01,27.81 56.01,26.8 55.75,26.54 54.61,26.54 54.36,26.8 54.36,29.46 55.37,30.48 55.37,31.5 55.5,31.62 57.02,31.62
GND on BOTTOM (solid shape): 85.5,42.06 85.5,37.06 85.72,36.83 85.72,31.62 85.47,31.37 75.9,31.37 75.59,31.67 75.59,39.8 76.17,40.39 82.22,40.39 83.19,41.35 83.19,42.16 83.31,42.29 85.27,42.29
GND on BOTTOM (solid shape): 80.26,48.26 80.26,45.72 80.14,45.59 76.83,45.59 76.33,46.1 75.56,46.1 75.44,46.23 76.2,46.23 76.2,46.61 75.82,46.61 75.82,46.23 75.44,46.23 75.44,48.13 75.69,48.39 80.14,48.39
GND on BOTTOM (solid shape): 59.05,18.29 59.05,13.46 58.93,13.34 57.78,13.34 57.66,13.46 57.66,15.16 57.71,15.37 57.66,15.57 57.66,18.29 57.78,18.41 58.93,18.41
GND on BOTTOM (solid shape): 120.02,106.3 120.02,105.16 119.94,105.08 119.51,105.08 119.46,105.03 119.38,105.03 118.87,104.52 118.87,102.74 118.75,102.62 117.98,102.62 117.6,103 117.6,103.12 118.75,103.12 118.75,103.5 118.36,103.5 118.36,103.12 117.6,103.12 117.6,103.76 118.75,103.76 118.75,104.14 118.36,104.14 118.36,103.76 117.6,103.76 117.6,106.17 117.86,106.43 119.89,106.43
GND on BOTTOM (solid shape): 61.34,45.28 61.34,43.81 62.23,42.93 70.48,42.93 70.87,43.31 73.28,43.31 73.53,43.05 73.53,39.24 73.03,38.73 70.99,38.73 70.74,38.48 70.74,33.27 70.61,33.15 62.1,33.15 60.58,34.67 60.58,34.92 60.83,35.18 63.63,35.18 64.64,36.2 64.64,39.37 64.26,39.75 61.72,39.75 61.34,39.37 61.34,39.12 60.96,38.73 59.56,38.73 59.31,38.99 59.31,45.34 59.4,45.43 61.18,45.43
GND on BOTTOM (solid shape): 53.59,64.64 53.59,61.85 53.47,61.72 50.67,61.72 50.55,61.85 50.55,62.14 50.56,62.16 50.58,62.21 50.61,62.25 50.62,62.3 50.63,62.36 50.64,62.41 50.64,62.56 50.63,62.61 50.62,62.66 50.6,62.72 50.58,62.77 50.55,62.83 50.55,63.16 50.56,63.18 50.58,63.22 50.61,63.27 50.62,63.32 50.63,63.37 50.64,63.43 50.64,63.57 50.63,63.63 50.62,63.68 50.6,63.73 50.58,63.78 50.55,63.84 50.55,64.18 50.56,64.19 50.58,64.24 50.61,64.29 50.62,64.34 50.63,64.39 50.64,64.44 50.64,64.59 50.63,64.64 50.62,64.71 50.67,64.77 53.47,64.77
GND on BOTTOM (solid shape): 81.53,62.74 81.53,57.78 81.92,57.4 82.8,57.4 83.24,56.97 82.74,56.46 80.64,56.46 80.47,56.43 80.32,56.33 79.68,55.69 79.58,55.54 79.55,55.37 79.68,55.04 80,54.91 80.18,54.94 80.33,55.04 80.83,55.55 82.93,55.55 83.11,55.58 83.25,55.68 84.14,56.57 84.23,56.69 84.27,56.83 84.27,56.84 86.23,58.8 86.23,59.69 86.61,60.07 90.81,60.07 91.06,59.82 91.06,52.07 90.93,51.94 79.63,51.94 79.12,52.45 79.12,56.13 79.31,56.26 79.43,56.45 79.63,56.64 79.63,62.61 79.88,62.87 81.41,62.87
GND on BOTTOM (solid shape): outline of 169 points within 39.12,45.97 52.45,52.7
GND on BOTTOM (solid shape): outline of 1038 points within 26.92,0.51 55.75,41.15
GND on BOTTOM (solid shape): outline of 3405 points within 0.51,0.51 139.49,109.49
GND on GND02 (solid shape): outline of 35350 points within 0.51,0.51 139.49,109.49
GND on ART03 (solid shape): outline of 18571 points within 0.51,0.51 139.49,109.49
GND on GND04 (solid shape): outline of 35351 points within 0.51,0.51 139.49,109.49
GND on POWER05 (solid shape): outline of 15990 points within 0.51,0.51 139.49,109.49
GND on ART06 (solid shape): 49.54,22.97 49.53,22.86 49.53,16.13 49.53,16.1 49.54,16.03 49.56,15.97 49.58,15.9 49.62,15.85 49.66,15.79 49.68,15.77 55.75,9.7 55.75,0.59 55.67,0.51 27.01,0.51 26.92,0.59 26.92,4.83 28.07,5.97 31.52,5.97 31.55,5.95 31.61,5.93 31.68,5.91 31.74,5.9 31.81,5.89 31.88,5.9 31.95,5.91 32.01,5.93 32.07,5.95 32.1,5.97 37.08,5.97 37.72,6.6 37.72,10.03 36.07,11.68 36.07,13.33 41.99,13.33 41.99,10.29 43.38,8.89 43.38,6.6 44.07,5.92 50.29,5.92 50.72,6.35 50.72,12.95 50.04,13.64 42.29,13.64 41.99,13.33 36.07,13.33 36.07,24.26 36.45,24.64 47.88,24.64
GND on ART06 (solid shape): outline of 1052 points within 3.94,35.69 31.5,65.15
GND on ART06 (solid shape): outline of 10177 points within 0.51,0.51 139.49,109.49
GND on GND07 (solid shape): outline of 35351 points within 0.51,0.51 139.49,109.49
GND on ART08 (solid shape): outline of 1226 points within 58.8,30.99 77.47,53.59
GND on ART08 (solid shape): outline of 16619 points within 0.51,0.51 139.49,109.49
GND on GND09 (solid shape): outline of 35351 points within 0.51,0.51 139.49,109.49
GND_SIGNAL on TOP (solid shape): 35.31,80.01 35.31,77.34 35.18,77.22 25.02,77.22 23.62,78.61 22.73,78.61 22.61,78.74 22.61,79.76 22.94,80.09 35.23,80.09
GND_SIGNAL on TOP (solid shape): 24.13,88.27 24.13,84.2 23.37,83.44 22.67,83.44 22.64,83.46 22.59,83.48 22.53,83.49 22.5,83.49 22,83.49 21.84,83.64 21.84,83.69 22.73,83.69 22.73,84.33 22.23,84.33 22.23,83.69 21.84,83.69 21.84,84.33 21.97,84.45 21.97,86.11 22.86,86.11 23.11,86.36 23.11,87.12 22.86,87.38 18.29,87.38 17.14,86.23 17.14,85.6 17.02,85.47 16.38,85.47 16.26,85.6 16.26,87.12 17.59,88.46 23.94,88.46
GND_SIGNAL on BOTTOM (solid shape): outline of 515 points within 21.62,76.96 35.31,92.95
GND_SIGNAL on GND02 (solid shape): outline of 1481 points within 12.32,76.96 35.31,93.98
GND_SIGNAL on ART03 (solid shape): outline of 1481 points within 12.32,76.96 35.31,93.98
GND_SIGNAL on GND04 (solid shape): outline of 1481 points within 12.32,76.96 35.31,93.98
GND_SIGNAL on ART06 (solid shape): outline of 1480 points within 12.32,76.96 35.31,93.98
GND_SIGNAL on GND07 (solid shape): outline of 1481 points within 12.32,76.96 35.31,93.98
GND_SIGNAL on ART08 (solid shape): outline of 1481 points within 12.32,76.96 35.31,93.98
GND_SIGNAL on GND09 (solid shape): outline of 1481 points within 12.32,76.96 35.31,93.98
VBAT on TOP (solid shape): 43.81,55.75 43.81,55.12 43.31,54.61 42.04,54.61 40.89,53.47 38.1,53.47 37.85,53.21 37.85,51.94 37.72,51.82 36.07,51.82 35.94,51.94 35.94,53.21 35.69,53.47 35.69,54.86 35.81,54.99 40.13,54.99 40.26,55.12 41.78,55.12 41.78,55.5 41.4,55.5 41.4,55.12 40.26,55.12 40.89,55.75 41.91,55.75 42.04,55.88 43.69,55.88
VBAT on TOP (solid shape): 59.84,21.74 59.84,20.8 60.21,20.44 60.22,20.41 60.25,20.36 60.28,20.32 60.32,20.28 60.37,20.24 60.41,20.21 60.44,20.2 61.28,19.37 61.28,13.21 61.85,12.64 61.85,12.45 61.72,12.32 59.69,12.32 59.56,12.45 59.56,17.81 59.39,17.98 59.39,18.54 59.94,18.54 59.94,18.92 59.56,18.92 59.56,18.54 59.39,18.54 59.39,19.77 59.25,19.91 59.25,21.76 59.31,21.82 59.77,21.82
VBAT on TOP (solid shape): 93.98,17.4 93.98,11.94 93.73,11.68 88.9,11.68 88.39,12.19 88.39,13.46 88.27,13.59 88.27,13.84 88.77,13.84 88.77,14.22 88.39,14.22 88.39,13.84 88.27,13.84 88.27,15.62 88.01,15.88 85.09,15.88 84.71,15.49 84.71,13.21 84.58,13.08 84.56,13.09 84.52,13.1 84.48,13.11 84.45,13.11 83.95,13.11 83.93,13.11 83.88,13.1 83.84,13.09 83.82,13.08 83.74,13.16 83.74,13.34 84.58,13.34 84.58,13.84 84.2,13.84 84.2,13.34 83.74,13.34 83.74,13.61 83.74,13.64 83.74,13.68 83.72,13.72 83.71,13.76 83.69,13.78 83.69,16.64 84.71,17.65 93.73,17.65
VBAT on BOTTOM (solid shape): 46.35,55.12 45.34,54.1 43.49,54.1 43.48,54.15 43.34,54.42 43.05,54.53 42.95,54.52 42.86,54.49 42.85,54.48 42.67,54.48 42.04,55.12 42.04,55.75 42.29,56.01 43.43,56.01 43.69,55.75 43.69,55.12 43.74,55.06 43.86,54.95 44.01,54.91 44.77,54.91 44.88,54.93 44.97,54.99 45.21,54.99 45.47,55.24 45.47,56.03 45.65,56.19 45.73,56.42 45.73,56.46 46.35,56.46
VBAT on BOTTOM (solid shape): outline of 1139 points within 59.56,6.1 92.58,18.03
VBAT on ART08 (solid shape): outline of 3804 points within 39.69,10.54 71.75,56.13
VBUS on TOP (solid shape): outline of 130 points within 36.83,5.87 50.04,13.46
VBUS on ART06 (solid shape): outline of 360 points within 42.29,6.22 50.42,13.34
VBUS on ART08 (solid shape): outline of 360 points within 42.29,6.22 50.42,13.34
VBUS_OUT on TOP (solid shape): 45.09,33.53 45.09,33.15 43.43,31.5 43.43,29.08 42.16,27.81 42.16,26.29 41.78,25.91 35.31,25.91 35.18,26.04 35.18,29.72 35.31,29.84 42.04,29.84 42.35,30.16 42.35,32.19 43.81,33.66 44.96,33.66
VBUS_OUT on TOP (solid shape): 59.82,33.27 59.82,32.38 59.99,32.21 60.63,32.21 60.71,32.13 60.71,26.62 59.84,25.76 59.84,24.99 59.79,24.94 59.28,24.94 59.26,24.97 59.26,26.5 59.27,26.52 59.29,26.58 59.3,26.64 59.3,26.7 59.29,26.76 59.27,26.82 59.26,26.84 59.26,27.1 59.18,27.18 58.17,27.18 58.04,27.3 58.04,30.35 57.47,30.92 57.47,31.11 58.04,31.11 58.04,31.5 57.66,31.5 57.66,31.11 57.47,31.11 57.47,31.56 57.28,31.75 57.28,32.26 58.42,33.4 59.69,33.4
VBUS_OUT on BOTTOM (solid shape): 60.71,33.02 60.71,28.45 60.45,28.19 58.42,28.19 58.04,28.57 58.04,31.62 57.91,31.75 57.51,31.75 57.44,31.78 57.37,31.8 57.35,31.8 57.28,31.88 57.28,32.38 58.29,33.4 60.33,33.4
VBUS_OUT on ART06 (solid shape): outline of 2296 points within 35.24,25.15 60.83,35.43
VCC_COMB on TOP (solid shape): 39.24,45.72 39.24,45.14 39.19,45.08 39.19,44.45 39.24,44.4 39.24,43.56 39.12,43.43 38.23,43.43 38.1,43.56 38.1,45.21 38.86,45.21 38.86,45.59 38.35,45.59 38.35,45.21 38.1,45.21 38.1,45.85 38.2,45.95 38.61,45.95 38.64,45.95 38.69,45.96 38.73,45.97 38.99,45.97
VCC_COMB on TOP (solid shape): outline of 298 points within 59.74,10.16 73.66,25.91
VCC_COMB on BOTTOM (solid shape): 72.14,25.35 72.14,16.89 71.88,16.64 68.2,16.64 68.07,16.76 68.07,25.27 68.45,25.65 71.83,25.65
VCC_COMB on BOTTOM (solid shape): 63.88,20.7 63.88,15.88 63.63,15.62 61.85,15.62 61.59,15.88 61.59,20.83 61.72,20.95 63.63,20.95
VCC_COMB on ART03 (solid shape): outline of 2281 points within 38.1,21.97 71.63,47.82
VCC_SYS on TOP (solid shape): 80.58,29.4 83.76,29.4 84.2,28.96 84.28,28.96 84.28,28.76 88.69,28.76 88.71,28.77 88.77,28.7 88.77,26.16 88.65,26.04 81.15,26.04 80.77,25.65 80.77,20.5 80.72,20.45 80.72,19.76 80.64,19.68 79.25,19.68 78.87,20.07 80.52,20.07 80.52,20.45 80.01,20.45 80.01,20.07 78.87,20.07 78.23,20.7 76.83,20.7 76.71,20.83 76.71,26.92 77.22,27.43 77.22,29.72 77.47,29.97 80.01,29.97
VDD1V2 on BOTTOM (solid shape): 55.37,73.99 56.19,73.99 56.26,73.91 56.26,73.03 56.05,72.82 55.99,72.84 55.92,72.85 55.85,72.85 55.79,72.84 55.73,72.82 55.68,72.8 55.63,72.77 55.58,72.73 55.54,72.69 55.5,72.64 55.47,72.59 55.45,72.54 55.43,72.48 55.42,72.42 55.42,72.36 55.43,72.29 55.45,72.23 55.48,72.16 55.5,72.14 55.5,70.23 55.27,70 55.25,69.99 55.21,69.96 55.2,69.95 55,69.74 54.98,69.72 54.61,69.72 54.48,69.85 54.48,70.87 55.24,70.87 55.24,71.25 54.86,71.25 54.86,70.87 54.48,70.87 54.48,71.88 55.24,71.88 55.24,72.26 54.86,72.26 54.86,71.88 54.48,71.88 54.48,72.9 55.24,72.9 55.24,73.28 54.86,73.28 54.86,72.9 54.48,72.9 54.48,73.41 55.12,74.04 55.32,74.04
VDD_MCU on TOP (solid shape): 66.29,54.36 66.29,53.84 66.28,53.81 66.27,53.75 66.27,53.72 66.27,53.21 66.27,53.18 66.28,53.13 66.29,53.09 66.29,49.53 66.17,49.4 64.52,49.4 64.39,49.53 64.39,50.8 63.37,51.82 63.37,53.47 66.04,53.47 66.04,53.85 65.53,53.85 65.53,53.47 63.37,53.47 63.37,54.36 63.5,54.48 66.17,54.48
VDD_MCU on BOTTOM (solid shape): 66.29,54.36 66.29,50.55 66.17,50.42 64.64,50.42 63.37,51.69 63.37,54.24 63.61,54.48 66.17,54.48
VDD_MCU on POWER05 (solid shape): outline of 14015 points within 44.32,47.37 80.14,76.58
VDD_SDRAM on TOP (solid shape): 73.03,54.48 73.03,48.9 72.9,48.77 71.75,48.77 71.5,49.02 71.5,50.29 71.12,50.67 70.61,50.67 70.23,51.05 70.23,52.83 72.9,52.83 72.9,53.21 72.39,53.21 72.39,52.83 70.23,52.83 70.23,54.61 70.36,54.74 72.77,54.74
VDD_SDRAM on BOTTOM (solid shape): outline of 3161 points within 64.9,49.78 76.83,70.99
VDDD on TOP (solid shape): outline of 100 points within 40.41,34.16 54.11,42.48
BATP on TOP (solid shape): 88.59,4.12 88.59,2.87 88.39,2.67 87,2.67 86.87,2.79 86.87,3.43 88.39,3.43 88.39,3.81 88.01,3.81 88.01,3.43 86.87,3.43 86.87,4.06 87,4.19 88.52,4.19
BQ_AGND on TOP (solid shape): 56.26,24.46 56.92,24.46 56.97,24.41 56.97,23.9 56.95,23.88 56.08,23.88 55.58,24.38 54.1,24.38 53.92,24.21 53.92,22.91 53.37,22.35 53.37,22.1 53.24,21.97 52.32,21.97 52.07,21.72 52.07,15.49 58.17,9.4 61.47,9.4 61.59,9.27 61.59,3.81 61.72,3.68 63.12,3.68 63.25,3.81 63.25,9.91 63.5,10.16 64.05,10.16 66.29,7.92 66.29,0.59 66.21,0.51 56.85,0.51 56.77,0.59 56.77,7.75 61.47,7.75 61.47,8.13 61.09,8.13 61.09,7.75 56.77,7.75 56.77,8.76 61.47,8.76 61.47,9.14 61.09,9.14 61.09,8.76 56.77,8.76 56.77,10.03 50.63,16.17 50.63,22.73 51.44,22.73 51.44,23.11 51.05,23.11 51.05,22.73 50.63,22.73 50.63,23.15 50.77,23.29 53.21,23.29 53.57,23.65 53.57,24.82 53.64,24.89 55.83,24.89
BQ_AGND on BOTTOM (solid shape): outline of 184 points within 50.55,0.51 66.29,25.02
BQ_AGND on GND02 (solid shape): outline of 257 points within 50.55,0.51 66.29,25.02
BQ_AGND on ART03 (solid shape): outline of 257 points within 50.55,0.51 66.29,25.02
BQ_AGND on GND04 (solid shape): outline of 257 points within 50.55,0.51 66.29,25.02
BQ_AGND on POWER05 (solid shape): outline of 257 points within 50.55,0.51 66.29,25.02
BQ_AGND on ART06 (solid shape): outline of 209 points within 50.55,0.51 66.29,25.02
BQ_AGND on GND07 (solid shape): outline of 257 points within 50.55,0.51 66.29,25.02
BQ_AGND on ART08 (solid shape): outline of 242 points within 50.55,0.51 66.29,25.02
BQ_AGND on GND09 (solid shape): outline of 257 points within 50.55,0.51 66.29,25.02
GAUGE_PULLUP on TOP (solid shape): 83.06,8.13 83.06,6.6 83.19,6.48 83.49,6.48 83.51,6.46 83.56,6.45 83.61,6.43 83.67,6.43 83.73,6.43 83.79,6.44 83.86,6.46 83.9,6.48 83.95,6.48 84.51,7.04 84.96,7.04 84.99,7.04 85.04,7.04 85.09,7.06 85.13,7.09 85.17,7.11 85.27,7.11 85.3,7.09 85.35,7.06 85.4,7.04 85.45,7.04 85.55,7.04 86.08,6.5 86.06,6.45 86.06,6.4 86.05,6.38 86.05,5.92 85.98,5.84 84.84,5.84 84.2,5.21 83.11,5.21 83.06,5.26 81.36,5.26 81.28,5.33 81.28,5.46 82.93,5.46 82.93,5.97 82.55,5.97 82.55,5.46 81.92,5.46 81.92,5.97 81.53,5.97 81.53,5.46 81.28,5.46 81.28,8.26 81.41,8.38 82.8,8.38
PHY_3V3 on TOP (solid shape): 12.19,73.03 12.19,71.66 11.92,71.39 11.9,71.37 11.87,71.32 11.85,71.28 11.68,71.12 11.68,68.96 11.43,68.71 10.16,68.71 9.91,68.96 9.91,68.98 9.93,69.03 9.93,69.07 9.93,69.34 10.54,69.34 10.54,69.72 10.16,69.72 10.16,69.34 9.93,69.34 9.93,69.6 9.93,69.63 9.92,69.68 9.91,69.72 9.91,69.85 10.03,69.98 10.03,71.5 10.54,71.5 10.54,71.88 10.16,71.88 10.16,71.5 10.03,71.5 10.03,72.52 10.54,72.52 10.54,72.9 10.16,72.9 10.16,72.52 10.03,72.52 10.03,73.03 10.16,73.15 12.06,73.15
PHY_3V3 on ART03 (solid shape): outline of 1114 points within 7.37,68.77 33.66,85.72
PMID on TOP (solid shape): 62.48,30.86 62.48,24.89 62.38,24.79 62.36,24.79 61.85,24.79 61.82,24.79 61.78,24.78 61.73,24.77 61.69,24.75 61.65,24.72 61.62,24.68 61.59,24.64 61.57,24.62 61.14,24.18 59.79,24.18 59.77,24.21 59.77,24.33 59.82,24.38 60.86,24.38 61.11,24.64 61.11,25.02 62.1,25.02 62.1,25.4 61.72,25.4 61.72,25.02 61.11,25.02 61.11,25.1 61.13,25.12 61.17,25.16 61.2,25.21 61.23,25.26 61.24,25.31 61.25,25.37 61.25,25.44 61.34,25.53 61.34,30.86 61.47,30.99 62.36,30.99
POWER_KEY on TOP (solid shape): 73.56,11.79 74.42,11.79 74.45,11.79 74.51,11.8 74.55,11.81 75.31,11.81 75.44,11.68 75.44,8 76.33,7.11 76.33,4.57 76.07,4.32 73.79,4.32 73.66,4.45 73.66,6.86 73.03,7.49 73.03,9.91 72.9,10.03 72.39,10.03 72.01,10.41 72.01,11.18 74.55,11.18 74.55,11.56 74.17,11.56 74.17,11.18 72.01,11.18 72.01,11.3 72.64,11.3 72.64,11.68 72.26,11.68 72.26,11.3 72.01,11.3 72.02,11.34 72.03,11.4 72.03,11.43 72.03,11.94 72.03,11.96 72.03,12 72.02,12.04 72.01,12.06 72.14,12.19 73.15,12.19
SDIO0_VDD_3.3V on TOP (solid shape): 38.86,93.85 38.86,91.06 39.88,90.04 39.88,88.39 39.62,88.14 37.72,88.14 37.59,88.27 37.59,88.39 38.35,88.39 38.35,88.77 37.85,88.77 37.85,88.39 37.59,88.39 37.61,88.43 37.62,88.49 37.62,88.52 37.62,89.03 37.62,89.06 37.61,89.11 37.59,89.15 37.59,89.41 38.35,89.41 38.35,89.79 37.85,89.79 37.85,89.41 37.59,89.41 37.61,89.45 37.62,89.51 37.62,89.53 37.62,90.04 37.62,90.07 37.61,90.13 37.59,90.17 37.59,90.42 38.35,90.42 38.35,90.81 37.85,90.81 37.85,90.42 37.59,90.42 37.61,90.46 37.62,90.52 37.62,90.55 37.62,91.06 37.62,91.08 37.61,91.12 37.6,91.16 37.59,91.19 38.1,91.69 38.1,93.85 38.23,93.98 38.73,93.98
N06481 on TOP (solid shape): 41.53,25.02 41.53,16.38 41.27,16.13 35.05,16.13 34.42,16.76 34.42,25.02 34.67,25.27 41.27,25.27
N06955 on TOP (solid shape): 45.85,22.23 45.85,21.08 45.72,20.95 44.2,20.95 43.81,20.57 42.8,20.57 42.67,20.7 42.67,22.35 42.8,22.48 45.59,22.48
N14548 on TOP (solid shape): 69.34,25.65 69.34,24.51 69.28,24.45 64.98,24.45 64.98,24.38 64.9,24.38 64.77,24.26 64.77,24 64.64,23.88 63.63,23.88 63.53,23.98 63.53,25.02 64.29,25.78 69.22,25.78
N14548 on TOP (solid shape): 59.54,24.59 59.54,23.95 59.56,23.93 60.73,23.93 60.76,23.9 60.76,23.75 60.73,23.72 58.57,23.72 58.47,23.83 58.47,24.66 58.52,24.71 59.41,24.71
N14548 on BOTTOM (solid shape): 64.77,25.02 64.77,24 64.64,23.88 63.63,23.88 63.5,24 63.5,25.02 63.63,25.15 64.64,25.15
N14548 on ART06 (solid shape): outline of 121 points within 58.42,23.75 65.15,26.8
N14944 on TOP (solid shape): 98.93,6.22 98.93,2.16 98.68,1.91 89.66,1.91 88.9,2.67 88.9,3.43 89.53,3.43 89.53,3.81 89.15,3.81 89.15,3.43 88.9,3.43 88.91,3.47 88.93,3.53 88.93,3.56 88.93,4.06 88.93,4.09 88.91,4.15 88.9,4.19 88.9,6.48 89.03,6.6 98.55,6.6
N14944 on BOTTOM (solid shape): 98.93,6.22 98.93,2.21 98.63,1.91 89.92,1.91 89.66,2.16 89.66,5.59 90.68,6.6 98.55,6.6
